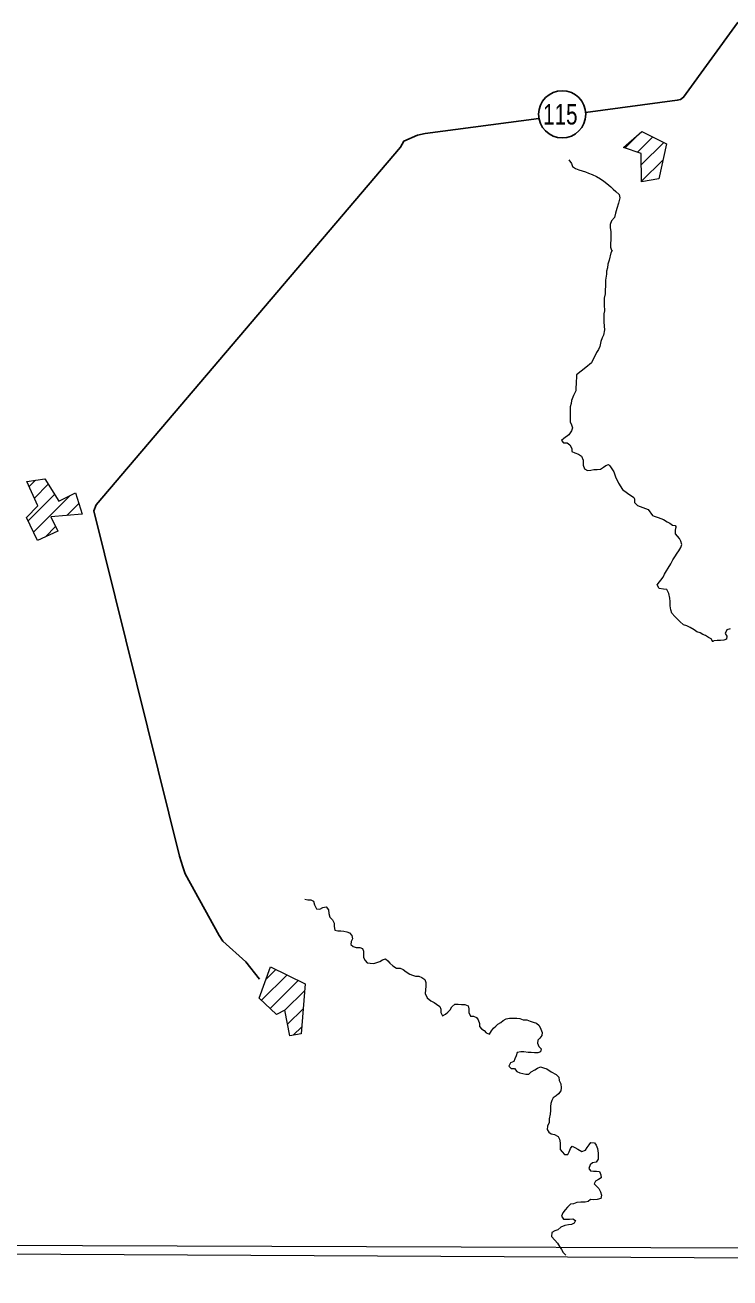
# Model space of a CAD drawing. Extents: x 553962 to 842807, y 8883888 to 9032388.
# Drawn here: x 611216 to 613616, y 8898711 to 8902976 of the extents above; entities that cross this region are included whole.
import ezdxf
from ezdxf.enums import TextEntityAlignment as Align

# ---------------------------------------------------------------- set-up
doc = ezdxf.new("R2010")
doc.units = 0
doc.header["$LTSCALE"] = 20
doc.layers.add('6', color=7, linetype='Continuous', lineweight=13)

msp = doc.modelspace()

# ---------------------------------------------------------------- linework, layer by layer
at = {"layer": '6'}
for p, q in [((613258.9, 8902557.48), (613307.33, 8902605.91)), ((613301.44, 8902543.45), (613353.46, 8902595.47)), ((613314.54, 8902499.98), (613391.56, 8902577)), ((613315.64, 8902444.51), (613388.66, 8902517.53)), ((611230.29, 8901404.83), (611252.2, 8901426.74)), ((611247.98, 8901365.95), (611294.78, 8901412.75)), ((611226.53, 8901287.93), (611316.77, 8901378.17)), ((611245.05, 8901249.88), (611370.11, 8901374.94)), ((611358.78, 8901307.05), (611399.54, 8901347.81)), ((611285.44, 8901233.71), (611320.47, 8901268.74)), ((613558.23, 8900878.21), (613557.89, 8900877)), ((612037, 8899727.61), (612070.67, 8899761.27)), ((612021.98, 8899656.02), (612108.61, 8899742.64)), ((612051.08, 8899628.55), (612146.55, 8899724.02)), ((612101.11, 8899622), (612167.86, 8899688.76)), ((612110.49, 8899574.82), (612163.17, 8899627.5)), ((612129.08, 8899536.84), (612158.49, 8899566.25))]:
    msp.add_line(p, q, dxfattribs=at)
for points in [[(618535.25, 8909853.32), (607574.31, 8909890.72), (607543.3, 8898835.28), (618504.23, 8898795.81)], [(613253.64, 8902559.22), (613316.14, 8902613.57), (613400.9, 8902572.47), (613374.27, 8902452.95), (613315.69, 8902442.01), (613313.76, 8902539.38)], [(611222.18, 8901422.65), (611283.21, 8901430.96), (611331.4, 8901355.16), (611388.03, 8901384.1), (611411.01, 8901311.66), (611304.38, 8901302.24), (611328.11, 8901252.83), (611258.75, 8901221.74), (611220.76, 8901299.77), (611260.01, 8901339.5)], [(612052.56, 8899770.16), (612169.69, 8899712.66), (612156.59, 8899541.5), (612118.41, 8899535.03), (612100.98, 8899622.65), (612072.66, 8899608.19), (612013.69, 8899663.84)]]:
    msp.add_lwpolyline(points, close=True, dxfattribs=at)
at = {"layer": '6', "lineweight": 25}
for points in [[(614884.27, 8904031.56), (614289.53, 8903510.23), (613661.03, 8902994.84), (613641.63, 8902983.67), (613458.32, 8902730.32), (613448.11, 8902723.21), (613436.89, 8902720.17), (613124.65, 8902678.86)], [(612965.84, 8902657.86), (612578.58, 8902606.62), (612553.09, 8902601.58), (612506.15, 8902581.29), (612494.87, 8902560.93), (611458.28, 8901343.31), (611451.07, 8901322.95), (611742.21, 8900146.69), (611753.28, 8900110), (611761.35, 8900086.55), (611876.73, 8899876.46), (611889.9, 8899857.08), (611968.09, 8899786.63), (612014.18, 8899728.56)]]:
    msp.add_lwpolyline(points, dxfattribs=at)
at = {"layer": '6'}
for points in [[(613067.78, 8902517.77), (613076.84, 8902504.48), (613080.84, 8902495.29), (613090.96, 8902488.1), (613102.13, 8902483.95), (613113.29, 8902479.81), (613124.45, 8902476.69), (613134.59, 8902471.53), (613147.78, 8902467.38), (613161.97, 8902460.16), (613175.15, 8902452.95), (613187.3, 8902444.73), (613197.41, 8902436.52), (613210.56, 8902425.24), (613218.65, 8902418.06), (613227.74, 8902409.85), (613238.86, 8902399.6), (613241.84, 8902388.38), (613236.62, 8902370.08), (613231.41, 8902351.78), (613226.21, 8902335.51), (613223.06, 8902321.27), (613212.81, 8902310.13), (613208.65, 8902296.92), (613208.58, 8902286.73), (613210.52, 8902272.46), (613210.45, 8902262.28), (613210.33, 8902244.97), (613210.24, 8902232.74), (613210.16, 8902220.52), (613213.14, 8902210.32), (613215.1, 8902208.54)], [(613214.89, 8902208.84), (613211.37, 8902200.76), (613205.09, 8902175.34), (613200.93, 8902162.12), (613199.82, 8902149.91), (613195.68, 8902138.73), (613195.61, 8902128.55), (613192.42, 8902108.2), (613192.27, 8902087.83), (613191.17, 8902074.59), (613191.07, 8902061.35), (613187.92, 8902046.1), (613187.84, 8902034.89), (613187.76, 8902023.69), (613188.93, 8902003.73), (613187.55, 8901993.14), (613187.47, 8901980.92), (613187.36, 8901965.64), (613188.28, 8901951.38), (613189.21, 8901939.15), (613185.45, 8901921), (613180.88, 8901911.7), (613176.73, 8901899.5), (613173.56, 8901882.21), (613169.42, 8901872.05), (613162.23, 8901861.91), (613144.78, 8901826.26), (613125.24, 8901810.61), (613093.55, 8901785.94), (613093.48, 8901775.76), (613092.38, 8901763.54), (613092.31, 8901753.36), (613092.24, 8901743.18), (613092.15, 8901730.95), (613083.9, 8901714.71), (613076.67, 8901698.46), (613075.58, 8901688.28), (613072.45, 8901676.08), (613072.36, 8901663.86), (613072.25, 8901647.56), (613072.17, 8901635.34), (613072.1, 8901625.15), (613077.11, 8901614.94), (613080.09, 8901604.74), (613076.97, 8901594.57), (613067.72, 8901581.39), (613051.36, 8901568.25), (613043.18, 8901562.19), (613050.24, 8901553.99), (613062.45, 8901553.92), (613071.55, 8901546.73), (613077.57, 8901534.48), (613078.52, 8901524.29), (613088.66, 8901520.15), (613100.83, 8901514.98), (613110.96, 8901508.81), (613116.97, 8901495.53), (613116.85, 8901478.22), (613120.83, 8901464.95), (613130.96, 8901459.8), (613143.18, 8901460.74), (613153.37, 8901463.74), (613164.56, 8901463.67), (613175.75, 8901464.62), (613185.97, 8901470.67), (613194.15, 8901476.73), (613203.33, 8901480.74)], [(613203.33, 8901480.74), (613207.46, 8901475.34), (613220.8, 8901455.03), (613226.99, 8901438.76), (613237.28, 8901416.39), (613250.62, 8901395.06), (613267.99, 8901382.93), (613288.85, 8901367.67)], [(613288.85, 8901367.67), (613291.08, 8901363.49), (613291.57, 8901350.45), (613301.8, 8901340.31), (613337.49, 8901327.28), (613352.86, 8901306.99), (613357.96, 8901303.96), (613372.23, 8901299.97), (613390.59, 8901292.95), (613402.85, 8901284.87)], [(613369.07, 8901070.68), (613389.4, 8901097.17), (613393.54, 8901107.33), (613400.74, 8901118.49), (613405.88, 8901127.63), (613415.14, 8901141.83), (613422.35, 8901156.05), (613428.53, 8901166.19), (613436.75, 8901178.37), (613442.91, 8901186.48), (613449.09, 8901197.65), (613452.21, 8901207.81), (613449.23, 8901219.04), (613444.21, 8901228.24), (613438.16, 8901236.42), (613431.09, 8901243.6), (613431.17, 8901254.8), (613432.26, 8901264.98), (613432.3, 8901265.01)], [(613402.85, 8901284.87), (613412.18, 8901280.76), (613421.29, 8901273.57), (613429.38, 8901273.01), (613432.19, 8901268.76), (613432.26, 8901264.98)], [(613557.89, 8900877), (613552.87, 8900886.19), (613543.75, 8900891.34), (613533.63, 8900897.52), (613524.5, 8900901.65), (613515.39, 8900906.8), (613503.21, 8900910.95), (613494.1, 8900917.12), (613480.94, 8900925.35), (613469.79, 8900930.52), (613458.63, 8900934.66), (613445.49, 8900945.95), (613428.31, 8900962.35), (613418.23, 8900974.64), (613415.26, 8900985.86), (613413.32, 8900999.11), (613412.4, 8901013.37), (613411.47, 8901025.6), (613408.53, 8901040.9), (613401.5, 8901054.18), (613390.32, 8901055.27), (613375.09, 8901058.42), (613369.07, 8901070.68), (613369.08, 8901071.98), (613369.07, 8901070.68)], [(613616.96, 8900920.39), (613605.75, 8900917.4), (613600.58, 8900905.21), (613605.6, 8900896.02), (613604.51, 8900885.84), (613595.33, 8900881.82), (613584.14, 8900880.88), (613572.95, 8900880.95), (613562.77, 8900879.99), (613558.23, 8900878.21)], [(612169.37, 8900000.74), (612179.08, 8899998.25), (612189.25, 8899998.19), (612198.37, 8899993.03), (612202.36, 8899980.78), (612208.37, 8899967.5), (612220.57, 8899966.4), (612230.78, 8899972.45), (612241.99, 8899974.42), (612249.04, 8899964.18), (612250.99, 8899951.95), (612253.95, 8899938.68), (612263.05, 8899930.47), (612269.07, 8899919.23), (612268.99, 8899907), (612270.94, 8899894.77), (612281.1, 8899892.66), (612291.27, 8899892.6), (612301.43, 8899891.51), (612311.59, 8899889.41), (612320.72, 8899885.28), (612328.8, 8899877.08), (612330.76, 8899865.86), (612326.62, 8899855.7), (612325.53, 8899845.51), (612333.63, 8899839.35), (612343.78, 8899836.23), (612355.98, 8899836.15), (612365.11, 8899832.02), (612369.12, 8899822.82), (612369.05, 8899812.64), (612368.97, 8899801.43), (612373.98, 8899791.21), (612381.06, 8899784.03), (612391.22, 8899782.95), (612403.42, 8899781.85), (612414.63, 8899784.84), (612424.82, 8899787.83), (612433, 8899793.89), (612443.2, 8899796.88), (612451.29, 8899790.71), (612458.36, 8899782.52), (612468.46, 8899773.28), (612480.61, 8899765.06), (612493.84, 8899764.97), (612503.98, 8899760.83), (612514.1, 8899752.62), (612526.25, 8899745.41), (612535.38, 8899741.27), (612545.53, 8899738.15), (612556.72, 8899738.08), (612567.88, 8899733.93), (612578.01, 8899726.74), (612580.99, 8899716.53), (612580.9, 8899704.31), (612579.8, 8899692.09), (612578.69, 8899678.85), (612585.72, 8899664.54), (612597.85, 8899654.28), (612609.01, 8899649.11), (612617.1, 8899642.95), (612628.23, 8899634.73), (612632.24, 8899625.53), (612632.16, 8899614.32), (612638.19, 8899603.08), (612648.4, 8899609.13), (612655.57, 8899616.21), (612663.76, 8899623.29), (612669.93, 8899633.44), (612679.15, 8899642.55), (612691.36, 8899642.47), (612702.54, 8899641.38), (612713.73, 8899641.31), (612724.89, 8899637.16), (612727.87, 8899626.95), (612727.79, 8899614.73), (612732.79, 8899602.47), (612742.96, 8899602.41), (612753.1, 8899597.25), (612759.14, 8899589.06), (612763.13, 8899576.81), (612764.08, 8899566.62), (612770.12, 8899558.43), (612779.24, 8899553.27), (612786.31, 8899545.08), (612797.47, 8899540.93), (612804.67, 8899552.09), (612810.83, 8899561.22), (612819.02, 8899568.3), (612826.19, 8899575.39), (612836.39, 8899580.41), (612844.58, 8899587.49), (612854.79, 8899592.52), (612866, 8899595.51), (612877.19, 8899595.43), (612890.41, 8899595.35), (612900.58, 8899594.27), (612912.75, 8899590.11), (612924.96, 8899590.03), (612936.11, 8899584.87), (612946.27, 8899581.75)], [(612946.27, 8899581.75), (612957.43, 8899578.62), (612966.53, 8899570.41), (612972.55, 8899558.15), (612976.54, 8899546.91), (612975.45, 8899535.71), (612969.29, 8899527.6), (612962.12, 8899520.52), (612961.03, 8899510.34), (612966.04, 8899499.1), (612973.11, 8899490.9), (612971.81, 8899480.8), (612962.84, 8899477.73), (612950.64, 8899477.8), (612939.45, 8899477.88), (612929.28, 8899477.94), (612915.05, 8899480.07), (612903.87, 8899481.16), (612891.64, 8899478.18), (612888.51, 8899467), (612884.37, 8899456.83), (612880.24, 8899447.69), (612869.02, 8899443.69), (612863.85, 8899431.5), (612871.94, 8899424.31), (612883.13, 8899424.24), (612891.2, 8899414), (612901.34, 8899408.84), (612911.49, 8899406.74), (612921.65, 8899404.64), (612931.82, 8899404.57), (612940.02, 8899412.67), (612952.27, 8899419.72), (612961.46, 8899424.76), (612971.67, 8899429.79), (612981.81, 8899425.65), (612992.98, 8899422.52), (613007.15, 8899412.24), (613024.38, 8899402.96), (613033.48, 8899394.75), (613035.43, 8899382.51), (613040.44, 8899371.28), (613041.36, 8899358.03), (613040.28, 8899347.85), (613033.09, 8899337.7), (613024.9, 8899330.62), (613014.69, 8899324.58), (613009.54, 8899315.44), (613006.42, 8899305.27), (613005.33, 8899295.09), (613005.23, 8899280.83), (613004.13, 8899268.61), (613000.97, 8899252.33), (613000.88, 8899240.11), (612995.71, 8899227.92), (612994.62, 8899216.72), (612999.64, 8899207.52), (613007.74, 8899201.35), (613018.91, 8899199.24), (613031.07, 8899192.03), (613036.09, 8899182.83), (613038.04, 8899170.59), (613037.96, 8899158.37), (613038.9, 8899148.17), (613044.95, 8899139.99), (613053.03, 8899130.77), (613064.21, 8899130.69), (613069.36, 8899139.83), (613073.51, 8899151.01), (613079.67, 8899159.12), (613088.8, 8899154.99), (613098.93, 8899148.81), (613112.1, 8899141.59), (613124.33, 8899145.59), (613130.5, 8899154.72), (613136.67, 8899163.85), (613142.83, 8899171.96), (613155.03, 8899170.86), (613161.07, 8899162.67), (613165.06, 8899151.44), (613168.01, 8899136.14), (613167.94, 8899125.95), (613167.87, 8899115.77), (613160.67, 8899104.61), (613148.45, 8899102.65), (613140.27, 8899095.57), (613136.11, 8899083.37), (613142.16, 8899075.18), (613152.33, 8899074.1), (613162.5, 8899074.03), (613172.66, 8899072.95), (613176.65, 8899061.71), (613177.6, 8899051.52), (613169.42, 8899045.46), (613158.2, 8899040.44), (613154.07, 8899031.3), (613161.14, 8899024.12), (613170.23, 8899014.89), (613175.24, 8899003.65), (613179.23, 8898992.42), (613177.12, 8898981.23)], [(574695.3, 8898953.23), (596544.27, 8898870.44), (626625.69, 8898710.85)], [(613177.12, 8898981.23), (613164.89, 8898978.25), (613152.67, 8898976.29), (613141.49, 8898978.4), (613133.31, 8898971.32), (613123.12, 8898969.35), (613108.87, 8898968.42), (613095.64, 8898967.49), (613083.41, 8898963.49), (613073.23, 8898962.54), (613062.98, 8898951.4), (613055.8, 8898942.27), (613047.59, 8898932.14), (613043.45, 8898920.96), (613049.48, 8898910.73), (613059.65, 8898910.67), (613069.82, 8898910.6), (613081.02, 8898911.55), (613090.14, 8898906.4), (613086.01, 8898897.25), (613076.82, 8898893.24), (613066.64, 8898891.27), (613054.42, 8898889.31), (613040.13, 8898883.29), (613029.91, 8898875.2), (613020.72, 8898871.19), (613009.49, 8898865.15), (613008.38, 8898851.91), (613020.51, 8898839.61), (613029.59, 8898829.36), (613035.62, 8898818.11), (613042.67, 8898807.88), (613048.7, 8898797.65), (613056.78, 8898789.45), (613057.79, 8898788.43)]]:
    msp.add_lwpolyline(points, dxfattribs=at)
at = {"layer": '6', "lineweight": 25}
msp.add_circle((613045.26, 8902672.38), 80.26, dxfattribs=at)

# ---------------------------------------------------------------- texts
at = {"layer": '6', "width": 0.75}
msp.add_text('115', height=70, dxfattribs=at).set_placement((613038.94, 8902637.71), align=Align.CENTER)

doc.saveas('drawing.dxf')
